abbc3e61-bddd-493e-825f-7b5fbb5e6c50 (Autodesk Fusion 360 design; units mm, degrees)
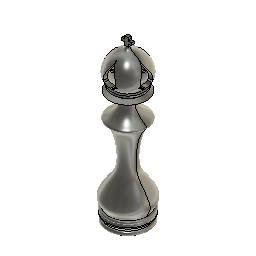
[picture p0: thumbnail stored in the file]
sketch "Sketch1" plane through (0, 0, 0) normal (0, 1, 0) x axis (1, 0, 0)
  line L1 (10, 0) -> (0, 0)
  line L2 (0, -80) -> (0, 0)
  line L3 (11.044, -3.7462) -> (10, -2.0881)
  line L4 (11.044, -4.3422) -> (11.044, -3.7462)
  line L5 (10, -5.6719) -> (11.044, -4.3422)
  curve K1 (4.3681, -57.7232) -> (10, -6.7215)
  line L6 (9.7131, -59.4804) -> (4.3681, -57.7232)
  line L7 (7.0406, -60.5055) -> (9.7131, -59.4804)
  line L8 (7.0406, -61.677) -> (7.0406, -60.5055)
  line L9 (8.3769, -61.677) -> (7.0406, -61.677)
  line L10 (8.3769, -62.702) -> (8.3769, -61.677)
  line L11 (7.0406, -62.702) -> (8.3769, -62.702)
  curve K2 (0.8588, -80) -> (7.0406, -62.702)
  line L12 (0.8588, -80) -> (0, -80)
  curve K3 (4.4239, -61.8049) -> (1.8516, -76.4261)
  line L13 (2.1675, -61.8049) -> (4.4239, -61.8049)
  curve K4 (1.8516, -76.4261) -> (2.1675, -61.8049)
  arc A1 centre (10, -1.044) radius 1.044 clockwise from (10, 0) to (10, -2.0881)
  arc A2 centre (10.5131, -6.1967) radius 0.7339 clockwise from (10, -5.6719) to (10, -6.7215)
  point P1 (0, 0)
  point P2 (0, 0)
  point P4 (0, 0)
  point P3 (10, 0)
  point P5 (0, -80)
  coincident P1 P2
  horizontal L1
  coincident P1 P4
  perpendicular L1 L2
  tangent L1 A1
  vertical L4
  perpendicular L8 L9
  perpendicular L10 L11
  perpendicular L2 L12
  horizontal L13
  dimension "d1" distance P2 P3 = 10
  dimension "d2" distance P4 P5 = 80
revolve "Revolve1" sketch "Sketch1" AlongAngle 360
work_plane "WorkPlane1" AlongDistance 11.962
sketch "Sketch2" plane through (11.962, 0, 0) normal (1, 0, 0) x axis (0, 1, 0)
  curve K1 (0, 76.0885) -> (-2.9886, 67.5703)
  line L1 (0, 76.0885) -> (0, 64.5817)
  curve K2 (0, 76.0885) -> (2.9886, 67.5703)
  curve K3 (-3.3816, 68.4508) -> (-2.5956, 66.6899)
  curve K4 (0.16, 77.0031) -> (-0.16, 75.1739)
  curve K5 (3.3816, 68.4508) -> (2.5956, 66.6899)
  curve K6 (-0.16, 77.0031) -> (0.16, 75.1739)
  line L2 (-4.0158, 67.1119) -> (-2.9886, 67.5703)
  line L3 (-2.8056, 66.5408) -> (-4.0158, 67.1119)
  line L4 (0, 63.2196) -> (-0.4047, 64.6093)
  line L5 (4.0158, 67.1119) -> (2.9886, 67.5703)
  line L6 (2.8056, 66.5408) -> (4.0158, 67.1119)
  line L7 (0, 63.2196) -> (0.4047, 64.6093)
  arc A1 centre (0, 67.5703) radius 2.9886 clockwise from (-0.4047, 64.6093) to (-2.8056, 66.5408)
  arc A2 centre (0, 67.5703) radius 2.9886 clockwise from (2.8056, 66.5408) to (0.4047, 64.6093)
  point P7 (0, 64.5817)
  point P3 (-2.9886, 67.5703)
  point P6 (0, 76.0885)
  point P8 (2.9886, 67.5703)
  point P4 (-2.9886, 69.854)
  point P9 (2.9886, 69.854)
  point P5 (-1.2185, 72.9519)
  point P10 (1.2185, 72.9519)
  point P11 (0, 76.0885)
  point P12 (-2.5956, 66.6899)
  point P16 (2.5956, 66.6899)
  point P13 (-3.3816, 68.4508)
  point P17 (3.3816, 68.4508)
  point P14 (-0.16, 75.1739)
  point P18 (0.16, 75.1739)
  point P15 (0.16, 77.0031)
  point P19 (-0.16, 77.0031)
  point P24 (2.9886, 67.5703)
  point P20 (-4.0158, 67.1119)
  point P25 (4.0158, 67.1119)
  point P21 (-2.8056, 66.5408)
  point P26 (2.8056, 66.5408)
  point P22 (-0.4047, 64.6093)
  point P27 (0.4047, 64.6093)
  point P23 (0, 63.2196)
  point P28 (0, 63.2196)
  coincident P7 A1
  vertical L1
  midpoint P3 K3
  midpoint P6 K4
  symmetric P3 L1 P8
  symmetric P4 L1 P9
  symmetric P5 L1 P10
  symmetric P6 L1 P11
  symmetric L1 P12 P16
  symmetric L1 P13 P17
  symmetric L1 P14 P18
  symmetric L1 P15 P19
  perpendicular K3 L2
  symmetric P3 L1 P24
  symmetric L1 P20 P25
  symmetric L1 P21 P26
  symmetric L1 P22 P27
  symmetric L1 P23 P28
  concentric A1 A2
extrude "Extrude1" cut sketch "Sketch2" profile of A2 K1 K2 L2 L3 L4 L5 L6 L7 against normal blind 25.302
circular_pattern "C-Pattern1" TotalAngle 90
sketch "Sketch3" plane through (0, 0, 0) normal (0, 1, 0) x axis (1, 0, 0)
  line L1 (-0.8574, -79.9405) -> (0.8209, -79.9405)
  line L2 (0.8209, -84.3936) -> (-0.8574, -84.3936)
  line L3 (2.5216, -81.5069) -> (2.5216, -82.8272)
  line L4 (-2.5581, -82.8272) -> (-2.5581, -81.5069)
  line L5 (0.8209, -83.2272) -> (0.8209, -84.3936)
  line L6 (0.8209, -79.9405) -> (0.8209, -81.1069)
  line L7 (-0.8574, -81.1069) -> (-0.8574, -79.9405)
  line L8 (-0.8574, -84.3936) -> (-0.8574, -83.2272)
  line L9 (-1.2574, -82.8272) -> (-2.5581, -82.8272)
  line L10 (2.5216, -82.8272) -> (1.2209, -82.8272)
  line L11 (1.2209, -81.5069) -> (2.5216, -81.5069)
  line L12 (-2.5581, -81.5069) -> (-1.2574, -81.5069)
  arc A1 centre (1.2209, -83.2272) radius 0.4 clockwise from (0.8209, -83.2272) to (1.2209, -82.8272)
  arc A2 centre (-1.2574, -83.2272) radius 0.4 clockwise from (-1.2574, -82.8272) to (-0.8574, -83.2272)
  arc A3 centre (-1.2574, -81.1069) radius 0.4 clockwise from (-0.8574, -81.1069) to (-1.2574, -81.5069)
  arc A4 centre (1.2209, -81.1069) radius 0.4 clockwise from (1.2209, -81.5069) to (0.8209, -81.1069)
  horizontal L1
  vertical L7
  horizontal L2
  vertical L5
  horizontal L9
  perpendicular L3 L9
  parallel L9 L11
  parallel L3 L4
  collinear L5 L6
  collinear L7 L8
  collinear L9 L10
  collinear L11 L12
  tangent L5 A1
  tangent L10 A1
  tangent L8 A2
  tangent L9 A2
  equal A1 A2
  tangent L7 A3
  tangent L12 A3
  equal A1 A3
  tangent L6 A4
  tangent L11 A4
  equal A1 A4
  dimension "d9" radius A1 = 0.4
extrude "Extrude2" add sketch "Sketch3" profile of L1 L8 L2 L6 L10 L3 L12 L4 A1 A2 A3 A4 distance 0.801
